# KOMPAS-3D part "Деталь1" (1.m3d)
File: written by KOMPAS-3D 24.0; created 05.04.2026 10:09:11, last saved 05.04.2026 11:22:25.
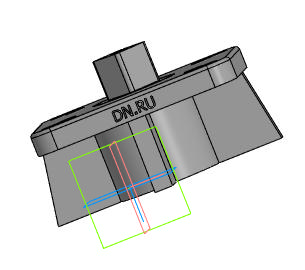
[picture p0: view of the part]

Document properties: Автор: R2D2; Полное имя файла: E:\Работа\Зайцев\Аксессуары для пневмоприводов\Ручной дублер DN.ru\MON3-700-T38-ISO Ручной дублер DN.ru\исходные материалы\1.m3d

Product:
- Body: Тело 2  | qty 1
    Масса: 2.451151
- Part/product: Деталь1
    Масса: 21.052029
    additional columns: Типовые

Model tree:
1. Операция без истории:1
2. Эскиз:1  (with: Ребро.Операция без истории:1)
3. Элемент выдавливания:1
     Расстояние 1 = 500
4. Эскиз:2  (with: Грань.Операция без истории:1, Ребро.Операция без истории:1)
5. Элемент выдавливания:2
     Расстояние 1 = 40
6. Эскиз:3  (with: Вершина.Операция без истории:1, Ребро.Операция без истории:1, Ребро.Элемент выдавливания:2)
7. Элемент выдавливания:3
     Расстояние 1 = 10
8. Массив по концентрической сетке:1  (with: Элемент выдавливания:3, Эскиз:3, Грань.Элемент выдавливания:2)  (4 pattern instances)
     Шаг 2 = 360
